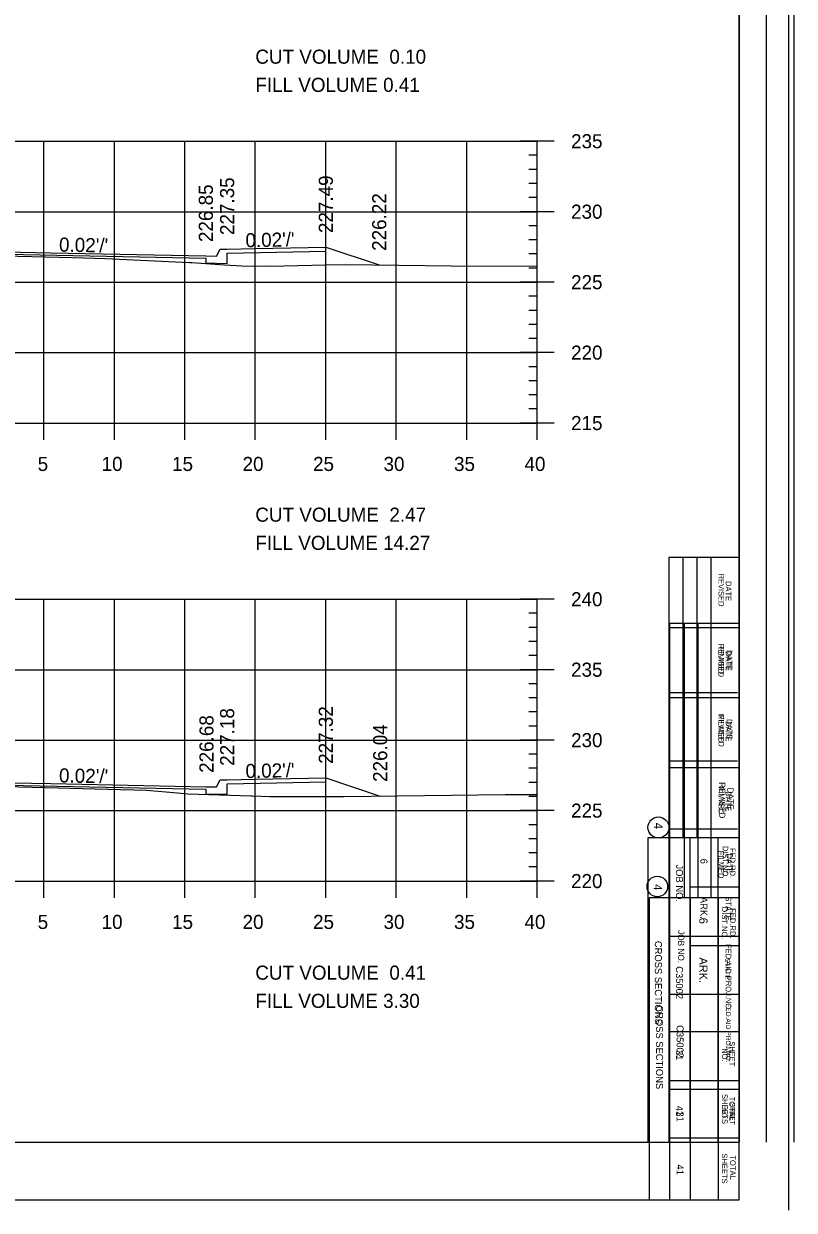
# Model space of a CAD drawing. Extents: x 1367903 to 1373764, y 376865 to 382130.
# Drawn here: x 1371275.8 to 1371385.1, y 377279.1 to 377447.5 of the extents above; entities that cross this region are included whole.
import ezdxf

# ---------------------------------------------------------------- set-up
doc = ezdxf.new("R2010")
doc.units = 0
for name, color, linetype in [('R_Axis', 7, 'Continuous'), ('R_Axis Annot', 7, 'Continuous'), ('R_Border', 7, 'Continuous'), ('R_Border Notes', 7, 'Continuous'), ('R_Border PE', 7, 'Continuous'), ('R_Exist Surface', 7, 'Continuous'), ('R_Fin Surface', 7, 'Continuous'), ('R_Fin Surface Annot', 7, 'Continuous'), ('R_Grid', 7, 'Continuous')]:
    doc.layers.add(name, color=color, linetype=linetype)

msp = doc.modelspace()

# ---------------------------------------------------------------- linework, layer by layer
for points in [[(1371232.63, 377415.53), (1371232.63, 377414.86), (1371232.63, 377414.86), (1371232.63, 377413.5), (1371235.63, 377413.56), (1371235.63, 377414.23), (1371268.63, 377414.89), (1371301.63, 377414.23), (1371301.63, 377413.56), (1371304.63, 377413.5), (1371304.63, 377414.94), (1371318.63, 377415.22), (1371318.63, 377415.81)], [(1371232.63, 377340.2), (1371232.63, 377339.53), (1371232.63, 377339.53), (1371232.63, 377338.17), (1371235.63, 377338.23), (1371235.63, 377338.9), (1371268.63, 377339.56), (1371301.63, 377338.9), (1371301.63, 377338.23), (1371304.63, 377338.17), (1371304.63, 377339.62), (1371318.63, 377339.9), (1371318.63, 377340.48)]]:
    msp.add_lwpolyline(points)
at = {"layer": 'R_Axis'}
for p, q in [((1371351.03, 377430.84), (1371346.23, 377430.84)), ((1371348.63, 377390.84), (1371348.63, 377430.84)), ((1371348.63, 377428.84), (1371347.43, 377428.84)), ((1371348.63, 377426.84), (1371347.43, 377426.84)), ((1371348.63, 377424.84), (1371347.43, 377424.84)), ((1371348.63, 377422.84), (1371347.43, 377422.84)), ((1371351.03, 377420.84), (1371346.23, 377420.84)), ((1371348.63, 377418.84), (1371347.43, 377418.84)), ((1371348.63, 377416.84), (1371347.43, 377416.84)), ((1371348.63, 377414.84), (1371347.43, 377414.84)), ((1371348.63, 377412.84), (1371347.43, 377412.84)), ((1371351.03, 377410.84), (1371346.23, 377410.84)), ((1371348.63, 377408.84), (1371347.43, 377408.84)), ((1371348.63, 377406.84), (1371347.43, 377406.84)), ((1371348.63, 377404.84), (1371347.43, 377404.84)), ((1371348.63, 377402.84), (1371347.43, 377402.84)), ((1371351.03, 377400.84), (1371346.23, 377400.84)), ((1371348.63, 377398.84), (1371347.43, 377398.84)), ((1371348.63, 377396.84), (1371347.43, 377396.84)), ((1371348.63, 377394.84), (1371347.43, 377394.84)), ((1371278.63, 377388.44), (1371278.63, 377393.24)), ((1371288.63, 377388.44), (1371288.63, 377393.24)), ((1371298.63, 377388.44), (1371298.63, 377393.24)), ((1371308.63, 377388.44), (1371308.63, 377393.24)), ((1371318.63, 377388.44), (1371318.63, 377393.24)), ((1371328.63, 377388.44), (1371328.63, 377393.24)), ((1371338.63, 377388.44), (1371338.63, 377393.24)), ((1371348.63, 377392.84), (1371347.43, 377392.84)), ((1371348.63, 377388.44), (1371348.63, 377393.24)), ((1371188.63, 377390.84), (1371348.63, 377390.84)), ((1371351.03, 377390.84), (1371346.23, 377390.84)), ((1371351.03, 377365.84), (1371346.23, 377365.84)), ((1371348.63, 377325.84), (1371348.63, 377365.84)), ((1371348.63, 377363.84), (1371347.43, 377363.84)), ((1371348.63, 377361.84), (1371347.43, 377361.84)), ((1371348.63, 377359.84), (1371347.43, 377359.84)), ((1371348.63, 377357.84), (1371347.43, 377357.84)), ((1371351.03, 377355.84), (1371346.23, 377355.84)), ((1371348.63, 377353.84), (1371347.43, 377353.84)), ((1371348.63, 377351.84), (1371347.43, 377351.84)), ((1371348.63, 377349.84), (1371347.43, 377349.84)), ((1371348.63, 377347.84), (1371347.43, 377347.84)), ((1371351.03, 377345.84), (1371346.23, 377345.84)), ((1371348.63, 377343.84), (1371347.43, 377343.84)), ((1371348.63, 377341.84), (1371347.43, 377341.84)), ((1371348.63, 377339.84), (1371347.43, 377339.84)), ((1371348.63, 377337.84), (1371347.43, 377337.84)), ((1371351.03, 377335.84), (1371346.23, 377335.84)), ((1371348.63, 377333.84), (1371347.43, 377333.84)), ((1371348.63, 377331.84), (1371347.43, 377331.84)), ((1371348.63, 377329.84), (1371347.43, 377329.84)), ((1371278.63, 377323.44), (1371278.63, 377328.24)), ((1371288.63, 377323.44), (1371288.63, 377328.24)), ((1371298.63, 377323.44), (1371298.63, 377328.24)), ((1371308.63, 377323.44), (1371308.63, 377328.24)), ((1371318.63, 377323.44), (1371318.63, 377328.24)), ((1371328.63, 377323.44), (1371328.63, 377328.24)), ((1371338.63, 377323.44), (1371338.63, 377328.24)), ((1371348.63, 377323.44), (1371348.63, 377328.24)), ((1371348.63, 377327.84), (1371347.43, 377327.84)), ((1371188.63, 377325.84), (1371348.63, 377325.84)), ((1371351.03, 377325.84), (1371346.23, 377325.84))]:
    msp.add_line(p, q, dxfattribs=at)
at = {"layer": 'R_Border'}
for p, q in [((1371384.3, 377620.35), (1371384.3, 377279.12)), ((1371377.26, 377280.59), (1371377.26, 377611.47)), ((1371377.26, 377446.03), (1371377.26, 377446.03)), ((1371367.44, 377280.59), (1371367.44, 377362.43)), ((1371367.44, 377362.43), (1371377.26, 377362.43)), ((1371367.44, 377362.43), (1371369.48, 377362.43)), ((1371369.48, 377362.43), (1371369.48, 377323.46)), ((1371371.42, 377362.43), (1371371.42, 377323.46)), ((1371373.28, 377362.43), (1371373.28, 377323.46)), ((1371367.44, 377352.62), (1371377.06, 377352.62)), ((1371367.44, 377342.9), (1371377.06, 377342.9)), ((1371367.44, 377333.27), (1371377.06, 377333.27)), ((1371377.26, 377323.46), (1371364.53, 377323.46)), ((1371364.53, 377323.46), (1371364.53, 377280.59)), ((1371370.36, 377280.59), (1371370.36, 377323.46)), ((1371374.34, 377280.59), (1371374.34, 377323.46)), ((1371377.26, 377316.65), (1371370.36, 377316.65)), ((1371377.26, 377309.75), (1371367.44, 377309.75)), ((1371377.26, 377296.24), (1371367.44, 377296.24)), ((1371377.26, 377289.33), (1371367.44, 377289.33)), ((1371172.93, 377280.59), (1371377.26, 377280.59))]:
    msp.add_line(p, q, dxfattribs=at)
msp.add_circle((1371365.67, 377325.07), 1.46, dxfattribs=at)
at = {"layer": 'R_Border PE'}
for p, q in [((1371381.18, 377288.8), (1371381.18, 377610.76)), ((1371385.1, 377288.8), (1371385.1, 377610.76)), ((1371377.26, 377603.25), (1371377.26, 377288.8)), ((1371367.31, 377371.74), (1371367.31, 377288.8)), ((1371377.26, 377371.74), (1371367.31, 377371.74)), ((1371369.3, 377371.74), (1371369.3, 377331.96)), ((1371371.29, 377371.74), (1371371.29, 377331.96)), ((1371373.28, 377371.74), (1371373.28, 377331.96)), ((1371377.26, 377361.8), (1371367.31, 377361.8)), ((1371377.26, 377351.85), (1371367.31, 377351.85)), ((1371377.26, 377341.91), (1371367.31, 377341.91)), ((1371377.26, 377331.96), (1371364.33, 377331.96)), ((1371364.33, 377331.96), (1371364.33, 377288.8)), ((1371370.29, 377331.96), (1371370.29, 377288.8)), ((1371374.27, 377331.96), (1371374.27, 377288.8)), ((1371370.36, 377325), (1371377.26, 377325)), ((1371367.44, 377318.04), (1371377.26, 377318.04)), ((1371367.44, 377304.51), (1371377.26, 377304.51)), ((1371367.44, 377297.55), (1371377.26, 377297.55)), ((1371172.93, 377288.8), (1371377.26, 377288.8)), ((1371374.37, 377288.8), (1371374.37, 377288.8))]:
    msp.add_line(p, q, dxfattribs=at)
msp.add_circle((1371365.82, 377333.45), 1.49, dxfattribs=at)
at = {"layer": 'R_Exist Surface'}
for points in [[(1371268.89, 377414.67), (1371278.91, 377414.42), (1371282.67, 377414.32), (1371287.38, 377414.2), (1371299.27, 377413.64), (1371299.5, 377413.62), (1371299.6, 377413.62), (1371304.27, 377413.28), (1371306.71, 377413.17), (1371310.69, 377413.11), (1371318.62, 377413.3), (1371321.59, 377413.35), (1371336.41, 377413.14), (1371348.63, 377413.13)], [(1371269.39, 377339.37), (1371280.68, 377339.07), (1371284.13, 377338.96), (1371293.17, 377338.72), (1371297.58, 377338.37), (1371299.06, 377338.23), (1371308.04, 377337.93), (1371308.2, 377337.92), (1371310.67, 377337.83), (1371319.97, 377337.85), (1371321.23, 377337.85), (1371344.09, 377338.11), (1371348.63, 377338.11)]]:
    msp.add_lwpolyline(points, dxfattribs=at)
at = {"layer": 'R_Fin Surface'}
for points in [[(1371230.73, 377414.9), (1371232.63, 377415.53), (1371233.63, 377415.53), (1371234.13, 377414.53), (1371235.63, 377414.56), (1371257.63, 377415), (1371268.63, 377415.22), (1371279.63, 377415), (1371301.63, 377414.56), (1371303.13, 377414.53), (1371303.63, 377415.53), (1371304.63, 377415.53), (1371308.63, 377415.61), (1371318.63, 377415.81), (1371326.21, 377413.28)], [(1371226.29, 377338.09), (1371232.63, 377340.2), (1371233.63, 377340.2), (1371234.13, 377339.2), (1371235.63, 377339.23), (1371257.63, 377339.67), (1371268.63, 377339.89), (1371279.63, 377339.67), (1371301.63, 377339.23), (1371303.13, 377339.2), (1371303.63, 377340.2), (1371304.63, 377340.2), (1371308.63, 377340.28), (1371318.63, 377340.48), (1371326.34, 377337.91)]]:
    msp.add_lwpolyline(points, dxfattribs=at)
at = {"layer": 'R_Grid'}
for p, q in [((1371188.63, 377430.84), (1371348.63, 377430.84)), ((1371278.63, 377390.84), (1371278.63, 377430.84)), ((1371288.63, 377390.84), (1371288.63, 377430.84)), ((1371298.63, 377390.84), (1371298.63, 377430.84)), ((1371308.63, 377390.84), (1371308.63, 377430.84)), ((1371318.63, 377390.84), (1371318.63, 377430.84)), ((1371328.63, 377390.84), (1371328.63, 377430.84)), ((1371338.63, 377390.84), (1371338.63, 377430.84)), ((1371348.63, 377390.84), (1371348.63, 377430.84)), ((1371188.63, 377420.84), (1371348.63, 377420.84)), ((1371188.63, 377410.84), (1371348.63, 377410.84)), ((1371188.63, 377400.84), (1371348.63, 377400.84)), ((1371188.63, 377390.84), (1371348.63, 377390.84)), ((1371188.63, 377365.84), (1371348.63, 377365.84)), ((1371278.63, 377325.84), (1371278.63, 377365.84)), ((1371288.63, 377325.84), (1371288.63, 377365.84)), ((1371298.63, 377325.84), (1371298.63, 377365.84)), ((1371308.63, 377325.84), (1371308.63, 377365.84)), ((1371318.63, 377325.84), (1371318.63, 377365.84)), ((1371328.63, 377325.84), (1371328.63, 377365.84)), ((1371338.63, 377325.84), (1371338.63, 377365.84)), ((1371348.63, 377325.84), (1371348.63, 377365.84)), ((1371188.63, 377355.84), (1371348.63, 377355.84)), ((1371188.63, 377345.84), (1371348.63, 377345.84)), ((1371188.63, 377335.84), (1371348.63, 377335.84)), ((1371188.63, 377325.84), (1371348.63, 377325.84))]:
    msp.add_line(p, q, dxfattribs=at)

# ---------------------------------------------------------------- texts
at = {"layer": 'R_Axis Annot'}
for s, p in [('CUT VOLUME  0.10', (1371308.63, 377441.84)), ('FILL VOLUME 0.41', (1371308.63, 377437.84)), ('235', (1371353.43, 377429.84)), ('230', (1371353.43, 377419.84)), ('225', (1371353.43, 377409.84)), ('220', (1371353.43, 377399.84)), ('215', (1371353.43, 377389.84)), ('5', (1371277.75, 377384.04)), ('10', (1371286.82, 377384.04)), ('15', (1371296.82, 377384.04)), ('20', (1371306.82, 377384.04)), ('25', (1371316.82, 377384.04)), ('30', (1371326.82, 377384.04)), ('35', (1371336.82, 377384.04)), ('40', (1371346.82, 377384.04)), ('CUT VOLUME  2.47', (1371308.63, 377376.84)), ('FILL VOLUME 14.27', (1371308.63, 377372.84)), ('240', (1371353.43, 377364.84)), ('235', (1371353.43, 377354.84)), ('230', (1371353.43, 377344.84)), ('225', (1371353.43, 377334.84)), ('220', (1371353.43, 377324.84)), ('5', (1371277.75, 377319.04)), ('10', (1371286.82, 377319.04)), ('15', (1371296.82, 377319.04)), ('20', (1371306.82, 377319.04)), ('25', (1371316.82, 377319.04)), ('30', (1371326.82, 377319.04)), ('35', (1371336.82, 377319.04)), ('40', (1371346.82, 377319.04)), ('CUT VOLUME  0.41', (1371308.63, 377311.84)), ('FILL VOLUME 3.30', (1371308.63, 377307.84))]:
    msp.add_text(s, height=2, dxfattribs=at).set_placement(p)
at = {"layer": 'R_Border'}
for s, height, p in [('REVISED', 0.778, (1371374.34, 377359.51)), ('DATE', 0.778, (1371375.51, 377358.64)), ('FILMED', 0.778, (1371374.34, 377349.41)), ('DATE', 0.778, (1371375.51, 377348.82)), ('REVISED', 0.875, (1371374.44, 377339.88)), ('DATE', 0.875, (1371375.61, 377339.1)), ('FILMED', 0.778, (1371374.34, 377330.16)), ('DATE', 0.778, (1371375.51, 377329.77)), ('4', 1.17, (1371365.15, 377325.4)), ('DIST.NO.', 0.778, (1371374.83, 377322.19)), ('FED.RD.', 0.778, (1371376, 377321.99)), ('6', 1.17, (1371371.62, 377320.63)), ('JOB NO.', 0.875, (1371368.61, 377318.88)), ('ARK.', 1.166, (1371371.62, 377315)), ('STATE', 0.681, (1371375.31, 377314.9)), ('FED.AID PROJ.NO.', 0.6805, (1371375.41, 377308.49)), ('NO.', 0.681, (1371374.83, 377293.61)), ('SHEET', 0.681, (1371376, 377294.39)), ('SHEETS', 0.778, (1371374.83, 377287.2)), ('TOTAL', 0.778, (1371376, 377286.91))]:
    msp.add_text(s, height=height, rotation=270, dxfattribs=at).set_placement(p)
at = {"layer": 'R_Border Notes'}
for s, height, p in [('CROSS SECTIONS', 0.9945, (1371365.49, 377308.2)), ('C35002', 0.995, (1371368.4, 377305.39)), ('31', 0.995, (1371368.41, 377293.15)), ('41', 0.995, (1371368.4, 377285.62))]:
    msp.add_text(s, height=height, rotation=270, dxfattribs=at).set_placement(p)
at = {"layer": 'R_Border PE'}
for s, height, p in [('REVISED', 0.796, (1371374.35, 377369.47)), ('DATE', 0.796, (1371375.38, 377368.41)), ('FILMED', 0.796, (1371374.35, 377359.12)), ('DATE', 0.796, (1371375.38, 377358.47)), ('REVISED', 0.796, (1371374.35, 377349.57)), ('DATE', 0.796, (1371375.38, 377348.52)), ('FILMED', 0.796, (1371374.35, 377339.23)), ('DATE', 0.796, (1371375.38, 377338.58)), ('4', 1.19, (1371365.22, 377334.12)), ('DIST.NO.', 0.796, (1371374.93, 377330.83)), ('FED.RD.', 0.796, (1371375.96, 377330.52)), ('JOB NO.', 0.995, (1371368.31, 377328.19)), ('6', 0.995, (1371371.79, 377329.02)), ('ARK.', 0.995, (1371371.79, 377323.6)), ('STATE', 0.796, (1371375.37, 377323.66)), ('CROSS SECTIONS', 0.9945, (1371365.32, 377317.35)), ('FED.AID PROJ.NO.', 0.7956, (1371375.37, 377316.88)), ('C35002', 0.995, (1371368.31, 377313.75)), ('SHEET', 0.796, (1371375.88, 377303.09)), ('31', 0.995, (1371368.31, 377301.87)), ('NO.', 0.796, (1371374.85, 377302.11)), ('SHEETS', 0.796, (1371374.85, 377295.62)), ('TOTAL', 0.796, (1371375.88, 377295.23)), ('41', 0.995, (1371368.31, 377293.96))]:
    msp.add_text(s, height=height, rotation=270, dxfattribs=at).set_placement(p)
at = {"layer": 'R_Fin Surface Annot'}
for s, rotation, p in [('227.49', 90, (1371319.63, 377417.81)), ('226.85', 90, (1371302.61, 377416.53)), ('227.35', 90, (1371305.63, 377417.53)), ('226.22', 90, (1371327.21, 377415.28)), ("0.02'/'", 1.1458, (1371307.25, 377415.78)), ("0.02'/'", 358.8542, (1371280.76, 377415.18)), ('227.18', 90, (1371305.63, 377342.2)), ('227.32', 90, (1371319.63, 377342.48)), ('226.68', 90, (1371302.7, 377341.2)), ('226.04', 90, (1371327.34, 377339.91)), ("0.02'/'", 358.8542, (1371280.76, 377339.85)), ("0.02'/'", 1.1458, (1371307.25, 377340.45))]:
    msp.add_text(s, height=2, rotation=rotation, dxfattribs=at).set_placement(p)

doc.saveas('drawing.dxf')
